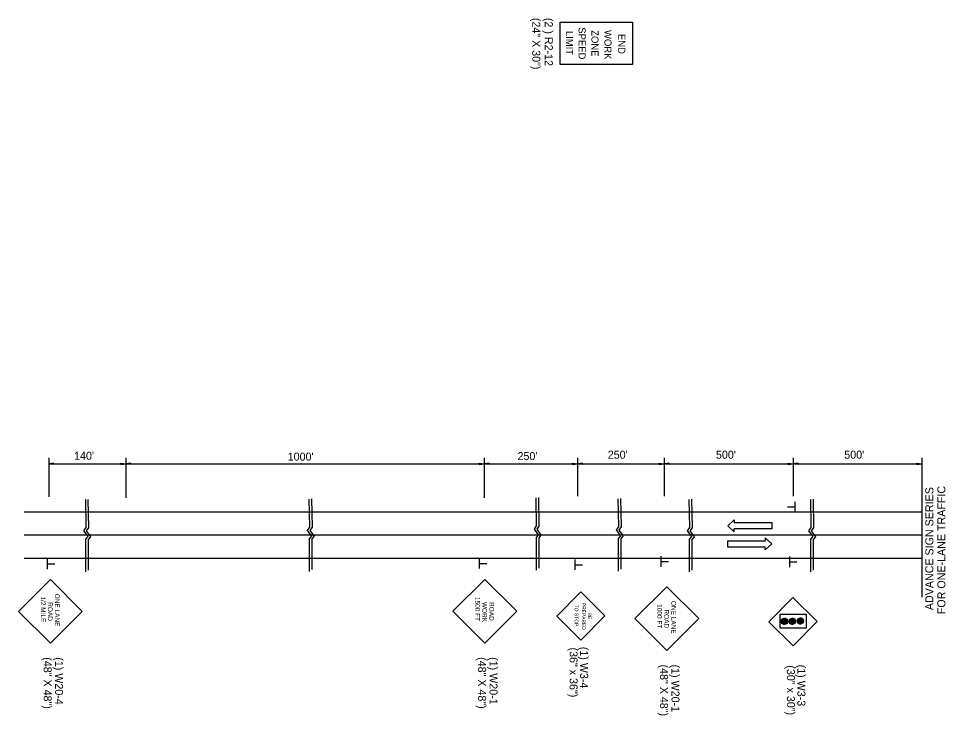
# Model space of a CAD drawing. Extents: x 1678017 to 1687792, y 404433 to 413488.
# Drawn here: x 1684233 to 1684929, y 410357 to 410880 of the extents above; entities that cross this region are included whole.
import ezdxf

# ---------------------------------------------------------------- set-up
doc = ezdxf.new("R2010")
doc.units = 0
doc.layers.add('Default', color=7, linetype='Continuous')
doc.layers.add('S_GRAVEL_ROAD', color=7, linetype='Continuous')

msp = doc.modelspace()

# ---------------------------------------------------------------- linework, layer by layer
at = {"layer": 'Default'}
for p, q in [((1684256.19, 410550.36), (1684256.19, 410521.01)), ((1684313.87, 410550.36), (1684313.87, 410520.36)), ((1684582.58, 410550.46), (1684582.58, 410520.45)), ((1684652.55, 410550.46), (1684652.55, 410521.65)), ((1684717.6, 410550.46), (1684717.6, 410521.65)), ((1684814.25, 410550.46), (1684814.25, 410521.65)), ((1684910.9, 410550.46), (1684910.9, 410445.9)), ((1684256.19, 410545.8), (1684313.87, 410545.78)), ((1684259.95, 410546.36), (1684256.2, 410545.8)), ((1684259.95, 410545.24), (1684256.2, 410545.8)), ((1684259.95, 410546.27), (1684256.82, 410545.8)), ((1684259.95, 410545.33), (1684256.82, 410545.8)), ((1684259.95, 410546.17), (1684257.47, 410545.8)), ((1684259.95, 410545.42), (1684257.47, 410545.8)), ((1684259.95, 410546.08), (1684258.09, 410545.8)), ((1684259.95, 410545.52), (1684258.09, 410545.8)), ((1684259.95, 410545.98), (1684258.73, 410545.8)), ((1684259.95, 410545.62), (1684258.73, 410545.8)), ((1684259.95, 410545.89), (1684259.35, 410545.8)), ((1684259.95, 410545.71), (1684259.35, 410545.8)), ((1684259.95, 410545.24), (1684259.95, 410546.36)), ((1684310.12, 410546.34), (1684313.87, 410545.78)), ((1684310.12, 410545.22), (1684310.12, 410546.34)), ((1684310.12, 410546.25), (1684313.24, 410545.78)), ((1684310.12, 410546.15), (1684312.6, 410545.78)), ((1684310.12, 410546.06), (1684311.97, 410545.78)), ((1684310.12, 410545.96), (1684311.34, 410545.78)), ((1684310.12, 410545.87), (1684310.71, 410545.78)), ((1684310.12, 410545.22), (1684313.87, 410545.78)), ((1684310.12, 410545.6), (1684311.34, 410545.78)), ((1684310.12, 410545.41), (1684312.6, 410545.78)), ((1684310.12, 410545.31), (1684313.24, 410545.78)), ((1684310.12, 410545.5), (1684311.97, 410545.78)), ((1684310.12, 410545.69), (1684310.71, 410545.78)), ((1684317.62, 410546.34), (1684313.87, 410545.78)), ((1684313.87, 410545.78), (1684582.58, 410545.78)), ((1684317.62, 410545.22), (1684313.87, 410545.78)), ((1684317.62, 410546.25), (1684314.49, 410545.78)), ((1684317.62, 410545.31), (1684314.49, 410545.78)), ((1684317.62, 410546.15), (1684315.14, 410545.78)), ((1684317.62, 410545.41), (1684315.14, 410545.78)), ((1684317.62, 410546.06), (1684315.76, 410545.78)), ((1684317.62, 410545.5), (1684315.76, 410545.78)), ((1684317.62, 410545.96), (1684316.4, 410545.78)), ((1684317.62, 410545.6), (1684316.4, 410545.78)), ((1684317.62, 410545.87), (1684317.03, 410545.78)), ((1684317.62, 410545.69), (1684317.03, 410545.78)), ((1684317.62, 410545.22), (1684317.62, 410546.34)), ((1684578.83, 410546.43), (1684582.58, 410545.87)), ((1684578.83, 410545.31), (1684578.83, 410546.43)), ((1684578.83, 410546.34), (1684581.95, 410545.87)), ((1684578.83, 410546.25), (1684581.31, 410545.87)), ((1684578.83, 410546.15), (1684580.68, 410545.87)), ((1684578.83, 410546.06), (1684580.05, 410545.87)), ((1684578.83, 410545.96), (1684579.42, 410545.87)), ((1684578.83, 410545.31), (1684582.58, 410545.87)), ((1684578.83, 410545.69), (1684580.05, 410545.87)), ((1684578.83, 410545.5), (1684581.31, 410545.87)), ((1684578.83, 410545.4), (1684581.95, 410545.87)), ((1684578.83, 410545.59), (1684580.68, 410545.87)), ((1684578.83, 410545.78), (1684579.42, 410545.87)), ((1684586.33, 410546.43), (1684582.58, 410545.87)), ((1684582.58, 410545.87), (1684652.49, 410545.87)), ((1684586.33, 410545.31), (1684582.58, 410545.87)), ((1684586.33, 410546.34), (1684583.21, 410545.87)), ((1684586.33, 410545.4), (1684583.21, 410545.87)), ((1684586.33, 410546.25), (1684583.85, 410545.87)), ((1684586.33, 410545.5), (1684583.85, 410545.87)), ((1684586.33, 410546.15), (1684584.48, 410545.87)), ((1684586.33, 410545.59), (1684584.48, 410545.87)), ((1684586.33, 410546.06), (1684585.11, 410545.87)), ((1684586.33, 410545.69), (1684585.11, 410545.87)), ((1684586.33, 410545.96), (1684585.74, 410545.87)), ((1684586.33, 410545.78), (1684585.74, 410545.87)), ((1684586.33, 410545.31), (1684586.33, 410546.43)), ((1684648.8, 410546.43), (1684652.55, 410545.87)), ((1684648.8, 410545.31), (1684648.8, 410546.43)), ((1684648.8, 410546.34), (1684651.92, 410545.87)), ((1684648.8, 410546.25), (1684651.27, 410545.87)), ((1684648.8, 410546.15), (1684650.65, 410545.87)), ((1684648.8, 410546.06), (1684650.01, 410545.87)), ((1684648.8, 410545.96), (1684649.39, 410545.87)), ((1684648.8, 410545.31), (1684652.55, 410545.87)), ((1684648.8, 410545.69), (1684650.01, 410545.87)), ((1684648.8, 410545.5), (1684651.27, 410545.87)), ((1684648.8, 410545.4), (1684651.92, 410545.87)), ((1684648.8, 410545.59), (1684650.65, 410545.87)), ((1684648.8, 410545.78), (1684649.39, 410545.87)), ((1684656.3, 410546.43), (1684652.55, 410545.87)), ((1684652.55, 410545.87), (1684717.89, 410545.87)), ((1684656.3, 410545.31), (1684652.55, 410545.87)), ((1684656.3, 410546.34), (1684653.17, 410545.87)), ((1684656.3, 410545.4), (1684653.17, 410545.87)), ((1684656.3, 410546.25), (1684653.82, 410545.87)), ((1684656.3, 410545.5), (1684653.82, 410545.87)), ((1684656.3, 410546.15), (1684654.44, 410545.87)), ((1684656.3, 410545.59), (1684654.44, 410545.87)), ((1684656.3, 410546.06), (1684655.08, 410545.87)), ((1684656.3, 410545.69), (1684655.08, 410545.87)), ((1684656.3, 410545.96), (1684655.7, 410545.87)), ((1684656.3, 410545.78), (1684655.7, 410545.87)), ((1684656.3, 410545.31), (1684656.3, 410546.43)), ((1684713.85, 410546.43), (1684717.6, 410545.87)), ((1684713.85, 410545.31), (1684713.85, 410546.43)), ((1684713.85, 410546.34), (1684716.97, 410545.87)), ((1684713.85, 410546.25), (1684716.33, 410545.87)), ((1684713.85, 410546.15), (1684715.7, 410545.87)), ((1684713.85, 410546.06), (1684715.07, 410545.87)), ((1684713.85, 410545.96), (1684714.44, 410545.87)), ((1684713.85, 410545.31), (1684717.6, 410545.87)), ((1684713.85, 410545.69), (1684715.07, 410545.87)), ((1684713.85, 410545.5), (1684716.33, 410545.87)), ((1684713.85, 410545.4), (1684716.97, 410545.87)), ((1684713.85, 410545.59), (1684715.7, 410545.87)), ((1684713.85, 410545.78), (1684714.44, 410545.87)), ((1684721.35, 410546.43), (1684717.6, 410545.87)), ((1684717.6, 410545.87), (1684815.08, 410545.87)), ((1684721.35, 410545.31), (1684717.6, 410545.87)), ((1684721.35, 410546.34), (1684718.22, 410545.87)), ((1684721.35, 410545.4), (1684718.22, 410545.87)), ((1684721.35, 410546.25), (1684718.87, 410545.87)), ((1684721.35, 410545.5), (1684718.87, 410545.87)), ((1684721.35, 410546.15), (1684719.49, 410545.87)), ((1684721.35, 410545.59), (1684719.49, 410545.87)), ((1684721.35, 410546.06), (1684720.13, 410545.87)), ((1684721.35, 410545.69), (1684720.13, 410545.87)), ((1684721.35, 410545.96), (1684720.75, 410545.87)), ((1684721.35, 410545.78), (1684720.75, 410545.87)), ((1684721.35, 410545.31), (1684721.35, 410546.43)), ((1684810.5, 410546.43), (1684814.25, 410545.87)), ((1684810.5, 410545.31), (1684810.5, 410546.43)), ((1684810.5, 410546.34), (1684813.62, 410545.87)), ((1684810.5, 410546.25), (1684812.98, 410545.87)), ((1684810.5, 410546.15), (1684812.35, 410545.87)), ((1684810.5, 410546.06), (1684811.72, 410545.87)), ((1684810.5, 410545.96), (1684811.09, 410545.87)), ((1684810.5, 410545.31), (1684814.25, 410545.87)), ((1684810.5, 410545.69), (1684811.72, 410545.87)), ((1684810.5, 410545.5), (1684812.98, 410545.87)), ((1684810.5, 410545.4), (1684813.62, 410545.87)), ((1684810.5, 410545.59), (1684812.35, 410545.87)), ((1684810.5, 410545.78), (1684811.09, 410545.87)), ((1684818, 410546.43), (1684814.25, 410545.87)), ((1684818, 410545.31), (1684814.25, 410545.87)), ((1684814.25, 410545.87), (1684910.9, 410545.87)), ((1684818, 410546.34), (1684814.87, 410545.87)), ((1684818, 410545.4), (1684814.87, 410545.87)), ((1684818, 410546.25), (1684815.52, 410545.87)), ((1684818, 410545.5), (1684815.52, 410545.87)), ((1684818, 410546.15), (1684816.14, 410545.87)), ((1684818, 410545.59), (1684816.14, 410545.87)), ((1684818, 410546.06), (1684816.78, 410545.87)), ((1684818, 410545.69), (1684816.78, 410545.87)), ((1684818, 410545.96), (1684817.41, 410545.87)), ((1684818, 410545.78), (1684817.41, 410545.87)), ((1684818, 410545.31), (1684818, 410546.43)), ((1684907.15, 410546.43), (1684910.9, 410545.87)), ((1684907.15, 410545.31), (1684907.15, 410546.43)), ((1684907.15, 410546.34), (1684910.27, 410545.87)), ((1684907.15, 410546.25), (1684909.63, 410545.87)), ((1684907.15, 410546.15), (1684909.01, 410545.87)), ((1684907.15, 410546.06), (1684908.37, 410545.87)), ((1684907.15, 410545.96), (1684907.74, 410545.87)), ((1684907.15, 410545.31), (1684910.9, 410545.87)), ((1684907.15, 410545.69), (1684908.37, 410545.87)), ((1684907.15, 410545.5), (1684909.63, 410545.87)), ((1684907.15, 410545.4), (1684910.27, 410545.87)), ((1684907.15, 410545.59), (1684909.01, 410545.87)), ((1684907.15, 410545.78), (1684907.74, 410545.87)), ((1684815.49, 410517.27), (1684815.49, 410509.45)), ((1684237.81, 410509.86), (1684306.59, 410509.86)), ((1684269.46, 410509.86), (1684336.07, 410509.86)), ((1684306.59, 410509.86), (1684340.84, 410509.86)), ((1684336.07, 410509.86), (1684405.08, 410509.86)), ((1684405, 410509.95), (1684471.62, 410509.95)), ((1684471.62, 410509.95), (1684540.62, 410509.95)), ((1684540.62, 410509.95), (1684614.56, 410509.95)), ((1684614.56, 410509.95), (1684676.54, 410509.95)), ((1684676.54, 410509.95), (1684737.38, 410509.95)), ((1684737.38, 410509.95), (1684823.99, 410509.95)), ((1684815.37, 410513.38), (1684810.03, 410513.38)), ((1684823.99, 410509.95), (1684910.9, 410509.95)), ((1684237.81, 410492.48), (1684307.35, 410492.48)), ((1684274.9, 410492.48), (1684336.07, 410492.48)), ((1684307.35, 410492.48), (1684346.28, 410492.48)), ((1684336.07, 410492.48), (1684410.44, 410492.57)), ((1684410.44, 410492.57), (1684471.62, 410492.57)), ((1684471.62, 410492.57), (1684540.62, 410492.57)), ((1684540.62, 410492.57), (1684615.02, 410492.57)), ((1684615.02, 410492.57), (1684676.2, 410492.57)), ((1684676.2, 410492.57), (1684737.38, 410492.57)), ((1684737.38, 410492.57), (1684823.99, 410492.57)), ((1684823.99, 410492.57), (1684910.9, 410492.57)), ((1684237.81, 410475.09), (1684306.64, 410475.09)), ((1684255.16, 410466.82), (1684255.16, 410474.64)), ((1684269.51, 410475.09), (1684336.07, 410475.09)), ((1684306.64, 410475.09), (1684340.9, 410475.09)), ((1684336.07, 410475.09), (1684405.08, 410475.09)), ((1684405.06, 410475.18), (1684471.62, 410475.18)), ((1684471.62, 410475.18), (1684540.62, 410475.18)), ((1684540.62, 410475.18), (1684615.48, 410475.18)), ((1684579.09, 410467.26), (1684579.09, 410475.09)), ((1684615.48, 410475.18), (1684675.86, 410475.18)), ((1684650.96, 410466.25), (1684650.96, 410474.08)), ((1684675.86, 410475.18), (1684750.2, 410475.18)), ((1684715.44, 410468.64), (1684715.44, 410476.46)), ((1684737.38, 410475.18), (1684833.16, 410475.18)), ((1684811.76, 410468.43), (1684811.76, 410476.25)), ((1684823.99, 410475.18), (1684910.9, 410475.18)), ((1684255.27, 410470.71), (1684260.61, 410470.71)), ((1684579.21, 410471.15), (1684584.55, 410471.15)), ((1684651.07, 410470.15), (1684656.41, 410470.15)), ((1684715.56, 410472.53), (1684720.9, 410472.53)), ((1684811.87, 410472.32), (1684817.21, 410472.32)), ((1684233.48, 410435.18), (1684257.36, 410459.08)), ((1684281.27, 410435.18), (1684257.36, 410459.08)), ((1684559.25, 410435.27), (1684583.14, 410459.18)), ((1684607.04, 410435.27), (1684583.14, 410459.18)), ((1684695.7, 410429.72), (1684719.58, 410453.62)), ((1684743.49, 410429.72), (1684719.58, 410453.62)), ((1684637.14, 410431.66), (1684655.16, 410449.73)), ((1684673.22, 410431.72), (1684655.16, 410449.73)), ((1684796.17, 410427.41), (1684814.18, 410445.48)), ((1684832.24, 410427.47), (1684814.18, 410445.48)), ((1684257.36, 410411.28), (1684233.48, 410435.18)), ((1684257.36, 410411.28), (1684281.27, 410435.18)), ((1684583.14, 410411.37), (1684559.25, 410435.27)), ((1684583.14, 410411.37), (1684607.04, 410435.27)), ((1684655.22, 410413.65), (1684637.14, 410431.66)), ((1684655.22, 410413.65), (1684673.22, 410431.72)), ((1684719.58, 410405.82), (1684695.7, 410429.72)), ((1684719.58, 410405.82), (1684743.49, 410429.72)), ((1684814.25, 410409.4), (1684796.17, 410427.41)), ((1684805.52, 410427.95), (1684808.02, 410425.45)), ((1684805.52, 410427.81), (1684807.89, 410425.44)), ((1684805.52, 410427.67), (1684807.74, 410425.44)), ((1684805.53, 410427.51), (1684807.59, 410425.45)), ((1684805.54, 410428.08), (1684808.15, 410425.46)), ((1684805.55, 410427.34), (1684807.42, 410425.48)), ((1684805.56, 410428.2), (1684808.28, 410425.48)), ((1684805.58, 410428.32), (1684808.39, 410425.51)), ((1684805.6, 410427.16), (1684807.23, 410425.52)), ((1684805.61, 410428.43), (1684808.51, 410425.54)), ((1684805.65, 410428.54), (1684808.62, 410425.57)), ((1684805.66, 410426.95), (1684807.02, 410425.59)), ((1684805.73, 410428.74), (1684808.82, 410425.65)), ((1684805.78, 410428.84), (1684808.92, 410425.7)), ((1684805.78, 410426.69), (1684806.76, 410425.7)), ((1684805.83, 410428.93), (1684809.01, 410425.75)), ((1684805.88, 410429.02), (1684809.1, 410425.81)), ((1684805.94, 410429.11), (1684809.18, 410425.86)), ((1684806, 410429.19), (1684809.27, 410425.92)), ((1684806.06, 410429.27), (1684809.34, 410425.99)), ((1684806.09, 410426.24), (1684806.31, 410426.01)), ((1684806.13, 410429.35), (1684809.42, 410426.05)), ((1684806.2, 410429.42), (1684809.49, 410426.13)), ((1684806.27, 410429.49), (1684809.56, 410426.2)), ((1684806.35, 410429.55), (1684809.63, 410426.27)), ((1684806.43, 410429.62), (1684809.69, 410426.35)), ((1684806.51, 410429.68), (1684809.75, 410426.44)), ((1684806.6, 410429.74), (1684809.81, 410426.52)), ((1684806.69, 410429.79), (1684809.87, 410426.61)), ((1684806.78, 410429.84), (1684809.92, 410426.71)), ((1684806.88, 410429.89), (1684809.96, 410426.8)), ((1684806.98, 410429.93), (1684810.01, 410426.9)), ((1684807.08, 410429.97), (1684810.04, 410427.01)), ((1684807.19, 410430), (1684810.08, 410427.12)), ((1684807.3, 410430.03), (1684810.11, 410427.23)), ((1684807.42, 410430.06), (1684810.13, 410427.35)), ((1684807.55, 410430.08), (1684810.15, 410427.47)), ((1684807.68, 410430.09), (1684810.17, 410427.6)), ((1684807.81, 410430.1), (1684810.17, 410427.74)), ((1684807.96, 410430.09), (1684810.17, 410427.88)), ((1684808.12, 410430.08), (1684810.16, 410428.04)), ((1684808.29, 410430.05), (1684810.13, 410428.21)), ((1684808.47, 410430.01), (1684810.09, 410428.4)), ((1684808.69, 410429.94), (1684810.01, 410428.61)), ((1684808.95, 410429.81), (1684809.89, 410428.88)), ((1684811.4, 410427.73), (1684813.7, 410425.44)), ((1684811.41, 410427.87), (1684813.84, 410425.44)), ((1684811.41, 410427.58), (1684813.55, 410425.45)), ((1684811.42, 410428.01), (1684813.97, 410425.45)), ((1684811.43, 410428.13), (1684814.1, 410425.47)), ((1684811.43, 410427.42), (1684813.39, 410425.47)), ((1684811.45, 410428.25), (1684814.22, 410425.49)), ((1684811.46, 410427.24), (1684813.21, 410425.5)), ((1684811.48, 410428.37), (1684814.33, 410425.52)), ((1684811.52, 410428.48), (1684814.44, 410425.55)), ((1684811.52, 410427.05), (1684813.01, 410425.55)), ((1684811.55, 410428.59), (1684814.55, 410425.59)), ((1684811.59, 410428.69), (1684814.65, 410425.63)), ((1684811.61, 410426.81), (1684812.78, 410425.64)), ((1684811.64, 410428.79), (1684814.75, 410425.67)), ((1684811.69, 410428.88), (1684814.85, 410425.72)), ((1684811.74, 410428.97), (1684814.94, 410425.78)), ((1684811.78, 410426.5), (1684812.46, 410425.82)), ((1684811.79, 410429.06), (1684815.02, 410425.83)), ((1684811.85, 410429.14), (1684815.11, 410425.89)), ((1684811.92, 410429.23), (1684815.19, 410425.95)), ((1684811.98, 410429.3), (1684815.27, 410426.02)), ((1684812.05, 410429.38), (1684815.34, 410426.09)), ((1684812.12, 410429.45), (1684815.41, 410426.16)), ((1684812.2, 410429.52), (1684815.48, 410426.23)), ((1684812.27, 410429.58), (1684815.55, 410426.31)), ((1684812.35, 410429.65), (1684815.61, 410426.39)), ((1684812.44, 410429.7), (1684815.67, 410426.47)), ((1684812.53, 410429.76), (1684815.72, 410426.56)), ((1684812.62, 410429.81), (1684815.78, 410426.65)), ((1684812.71, 410429.86), (1684815.83, 410426.75)), ((1684812.81, 410429.91), (1684815.87, 410426.85)), ((1684812.91, 410429.95), (1684815.91, 410426.95)), ((1684813.02, 410429.98), (1684815.95, 410427.05)), ((1684813.13, 410430.02), (1684815.98, 410427.16)), ((1684813.24, 410430.04), (1684816.01, 410427.28)), ((1684813.36, 410430.07), (1684816.03, 410427.4)), ((1684813.49, 410430.08), (1684816.05, 410427.53)), ((1684813.62, 410430.09), (1684816.06, 410427.66)), ((1684813.77, 410430.1), (1684816.06, 410427.8)), ((1684813.92, 410430.09), (1684816.05, 410427.95)), ((1684814.08, 410430.07), (1684816.03, 410428.11)), ((1684814.25, 410430.04), (1684816, 410428.29)), ((1684814.25, 410409.4), (1684832.24, 410427.47)), ((1684814.45, 410429.98), (1684815.95, 410428.49)), ((1684814.69, 410429.89), (1684815.86, 410428.72)), ((1684815, 410429.72), (1684815.69, 410429.04)), ((1684817.47, 410428.09), (1684819.9, 410425.65)), ((1684817.47, 410427.95), (1684819.76, 410425.65)), ((1684817.47, 410427.8), (1684819.61, 410425.66)), ((1684817.48, 410428.22), (1684820.03, 410425.66)), ((1684817.49, 410427.63), (1684819.45, 410425.68)), ((1684817.5, 410428.35), (1684820.16, 410425.68)), ((1684817.52, 410428.47), (1684820.28, 410425.7)), ((1684817.53, 410427.46), (1684819.27, 410425.71)), ((1684817.55, 410428.58), (1684820.4, 410425.73)), ((1684817.58, 410428.69), (1684820.51, 410425.76)), ((1684817.58, 410427.26), (1684819.07, 410425.77)), ((1684817.62, 410428.8), (1684820.61, 410425.8)), ((1684817.66, 410428.9), (1684820.72, 410425.84)), ((1684817.67, 410427.03), (1684818.84, 410425.86)), ((1684817.7, 410429), (1684820.81, 410425.89)), ((1684817.75, 410429.09), (1684820.91, 410425.94)), ((1684817.8, 410429.19), (1684821, 410425.99)), ((1684817.84, 410426.71), (1684818.52, 410426.03)), ((1684817.86, 410429.27), (1684821.09, 410426.04)), ((1684817.92, 410429.36), (1684821.17, 410426.1)), ((1684817.98, 410429.44), (1684821.25, 410426.17)), ((1684818.04, 410429.52), (1684821.33, 410426.23)), ((1684818.11, 410429.59), (1684821.4, 410426.3)), ((1684818.18, 410429.66), (1684821.48, 410426.37)), ((1684818.26, 410429.73), (1684821.55, 410426.45)), ((1684818.34, 410429.8), (1684821.61, 410426.52)), ((1684818.42, 410429.86), (1684821.67, 410426.6)), ((1684818.5, 410429.92), (1684821.73, 410426.69)), ((1684818.59, 410429.97), (1684821.79, 410426.78)), ((1684818.68, 410430.03), (1684821.84, 410426.87)), ((1684818.77, 410430.07), (1684821.89, 410426.96)), ((1684818.87, 410430.12), (1684821.93, 410427.06)), ((1684818.98, 410430.16), (1684821.97, 410427.16)), ((1684819.08, 410430.2), (1684822.01, 410427.27)), ((1684819.19, 410430.23), (1684822.04, 410427.38)), ((1684819.31, 410430.26), (1684822.07, 410427.49)), ((1684819.43, 410430.28), (1684822.09, 410427.61)), ((1684819.55, 410430.3), (1684822.11, 410427.74)), ((1684819.69, 410430.31), (1684822.12, 410427.87)), ((1684819.83, 410430.31), (1684822.12, 410428.01)), ((1684819.98, 410430.3), (1684822.12, 410428.16)), ((1684820.14, 410430.28), (1684822.1, 410428.33)), ((1684820.32, 410430.25), (1684822.06, 410428.5)), ((1684820.52, 410430.2), (1684822.01, 410428.7)), ((1684820.75, 410430.11), (1684821.92, 410428.93)), ((1684821.06, 410429.93), (1684821.75, 410429.25))]:
    msp.add_line(p, q, dxfattribs=at)
for points in [[(1684693.75, 410845.42), (1684639.68, 410845.42), (1684639.68, 410877.13), (1684693.75, 410877.13)], [(1684824.03, 410433.19), (1684824.03, 410422.66), (1684804.61, 410422.66), (1684804.61, 410433.19)]]:
    msp.add_lwpolyline(points, close=True, dxfattribs=at)
for points in [[(1684283.57, 410519.02), (1684283.89, 410497.99), (1684282.26, 410495.57), (1684285.43, 410491.24), (1684283.76, 410489.25), (1684283.76, 410464.79)], [(1684285.56, 410519.21), (1684285.88, 410497.91), (1684284.26, 410495.49), (1684287.42, 410491.16), (1684285.76, 410489.16), (1684285.75, 410466.19)], [(1684451.24, 410519.36), (1684451.56, 410498.32), (1684449.94, 410495.91), (1684453.1, 410491.58), (1684451.44, 410489.58), (1684451.43, 410465.12)], [(1684453.24, 410519.55), (1684453.56, 410498.24), (1684451.94, 410495.82), (1684455.1, 410491.49), (1684453.44, 410489.5), (1684453.43, 410466.53)], [(1684621.35, 410520.32), (1684621.67, 410499.28), (1684620.05, 410496.87), (1684623.21, 410492.54), (1684621.55, 410490.54), (1684621.54, 410466.08)], [(1684623.35, 410520.51), (1684623.67, 410499.2), (1684622.05, 410496.78), (1684625.21, 410492.45), (1684623.55, 410490.45), (1684623.54, 410467.49)], [(1684682.96, 410519.66), (1684683.28, 410498.63), (1684681.66, 410496.21), (1684684.82, 410491.88), (1684683.16, 410489.88), (1684683.15, 410465.43)], [(1684684.96, 410519.85), (1684685.28, 410498.54), (1684683.66, 410496.13), (1684686.82, 410491.8), (1684685.15, 410489.8), (1684685.15, 410466.83)], [(1684736.19, 410519.03), (1684736.51, 410497.99), (1684734.88, 410495.58), (1684738.05, 410491.25), (1684736.38, 410489.25), (1684736.37, 410464.79)], [(1684738.18, 410519.22), (1684738.5, 410497.91), (1684736.88, 410495.5), (1684740.04, 410491.17), (1684738.38, 410489.17), (1684738.37, 410466.2)], [(1684827.23, 410519.03), (1684827.55, 410497.99), (1684825.93, 410495.58), (1684829.09, 410491.25), (1684827.43, 410489.25), (1684827.42, 410464.79)], [(1684829.23, 410519.22), (1684829.55, 410497.91), (1684827.93, 410495.5), (1684831.09, 410491.17), (1684829.42, 410489.17), (1684829.42, 410466.2)]]:
    msp.add_lwpolyline(points, dxfattribs=at)
for centre in [(1684807.84, 410427.77), (1684813.73, 410427.77), (1684819.79, 410427.98)]:
    msp.add_circle(centre, 2.33, dxfattribs=at)
at = {"layer": 'S_GRAVEL_ROAD'}
for p, q in [((1684765.26, 410499.27), (1684770.23, 410503.8)), ((1684770.23, 410503.8), (1684770.23, 410501.54)), ((1684798.51, 410501.54), (1684770.23, 410501.54)), ((1684798.51, 410497.01), (1684798.51, 410501.54)), ((1684770.23, 410494.74), (1684765.26, 410499.27)), ((1684798.51, 410497.01), (1684770.23, 410497.01)), ((1684770.23, 410494.74), (1684770.23, 410497.01)), ((1684765.02, 410488.1), (1684793.31, 410488.1)), ((1684765.02, 410488.1), (1684765.02, 410483.57)), ((1684793.31, 410490.37), (1684798.28, 410485.84)), ((1684793.31, 410490.37), (1684793.31, 410488.1)), ((1684765.02, 410483.57), (1684793.31, 410483.57)), ((1684798.28, 410485.84), (1684793.31, 410481.31)), ((1684793.31, 410481.31), (1684793.31, 410483.57))]:
    msp.add_line(p, q, dxfattribs=at)

# ---------------------------------------------------------------- texts
at = {"layer": 'Default'}
for s, height, rotation, p in [('(24" X 30")', 6, 270, (1684618.71, 410880.33)), ('(2 ) R2-12', 6, 270, (1684628.12, 410880.33)), ('LIMIT', 5.319, 270, (1684644, 410870.56)), ('SPEED', 5.319, 270, (1684653.42, 410873.28)), ('ZONE', 5.319, 270, (1684663.07, 410871.08)), ('WORK ', 5.32, 270, (1684672.8, 410871.23)), ('END', 5.32, 270, (1684683.16, 410868.31)), ('ADVANCE SIGN SERIES', 6, 90, (1684919.46, 410436.08)), ('FOR ONE-LANE TRAFFIC', 6, 90, (1684928.46, 410433.05)), ('1/2 MILE', 3.522, 270.00057, (1684250.2, 410446.44)), ('ONE LANE', 3.521, 270.00045, (1684260.77, 410448.47)), ('ROAD', 3.52, 270.00004, (1684255.49, 410442.09)), ('1500 FT', 3.522, 270.00057, (1684575.98, 410445.99)), ('WORK', 3.52, 270.00004, (1684581.26, 410442.25)), ('ROAD', 3.521, 270.00045, (1684586.54, 410442.18)), ('TO STOP', 2.675, 270.00057, (1684650.53, 410440.19)), ('PREPARED', 2.658, 270.10034, (1684656, 410441.54)), ('1000 FT', 3.522, 270.00057, (1684712.42, 410440.58)), ('ONE LANE', 3.521, 270.00045, (1684722.99, 410443.02)), ('BE', 2.658, 270.10045, (1684660.45, 410434.08)), ('ROAD', 3.52, 270.00004, (1684717.71, 410436.63)), ('(36" x 36")', 6, 270, (1684646.71, 410408.07)), ('(1) W3-4', 6, 270, (1684654.61, 410408.61)), ('(48" X 48")', 6, 270, (1684252.32, 410400.76)), ('(1) W20-4', 6, 270, (1684260.88, 410400.76)), ('(48" X 48")', 6, 270, (1684578.09, 410400.86)), ('(1) W20-1', 6, 270, (1684586.65, 410400.86)), ('(48" X 48")', 6, 270, (1684714.53, 410395.3)), ('(1) W20-1', 6, 270, (1684723.1, 410395.3)), ('(30" x 30")', 6, 270, (1684809.64, 410394.69)), ('(1) W3-3', 6, 270, (1684817.53, 410395.22))]:
    msp.add_text(s, height=height, rotation=rotation, dxfattribs=at).set_placement(p)
for s, p in [("140'", (1684275.13, 410548.89)), ("1000'", (1684435.32, 410548.25)), ("250'", (1684607.64, 410548.65)), ("250'", (1684675.32, 410549.68)), ("500'", (1684756.44, 410549.68)), ("500'", (1684852.67, 410549.68))]:
    msp.add_text(s, height=6, dxfattribs=at).set_placement(p)

doc.saveas('drawing.dxf')
